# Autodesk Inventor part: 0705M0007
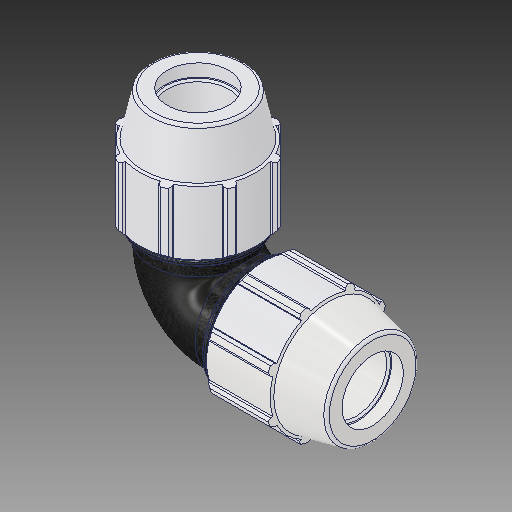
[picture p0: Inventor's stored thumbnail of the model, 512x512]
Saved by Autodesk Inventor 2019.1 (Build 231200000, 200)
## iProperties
Created: 2017-02
Part Number: 0705M0007
Material: PVC-Piping
Description: PLASSON 90° ELBOW 3/4'' - 3/4''
Document SubType Name: Modeling
Designer: KIM
Mass: 92.6774 g
Surface Area: 199.44 cm^2
Volume: 66.1981 cm^3
Density: 1.4 g/cm^3
Appearance: PTFE
Author: KIM
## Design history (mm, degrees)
derived "0705M0.ipt"
feature "Solid1::0705M0.ipt"
tag "TaggingFeature1"
body "Solid1"
other parameters: "d2" = 26.6, "d4" = 6.32883, "d5" = 18.9865, "d7" = 54.102, "d9" = 10.84943, "d11" = 1.89865, "d13" = 120 deg, "d14" = 39.9, "d15" = 12 deg, "d16" = 47.06874, "d18" = 1.33, "d19" = 35 deg, "d20" = 17.5 deg, "d21" = 50.31486, "d23" = 0, "d25" = 360 deg, "d27" = 1.08204, "d33" = 0.532, "d42" = 28.10002, "d43" = 1.62306, "d46" = 0.798, "d51" = 75.946, "d59" = 90 deg, "d63" = 56.896, "d64" = 23.94, "d67" = 40.5765, "d68" = 1.89865, "d70" = 90 deg, "d_" = 26.6, "E_" = 54.102, "A_" = 75.946, "l_" = 56.896
